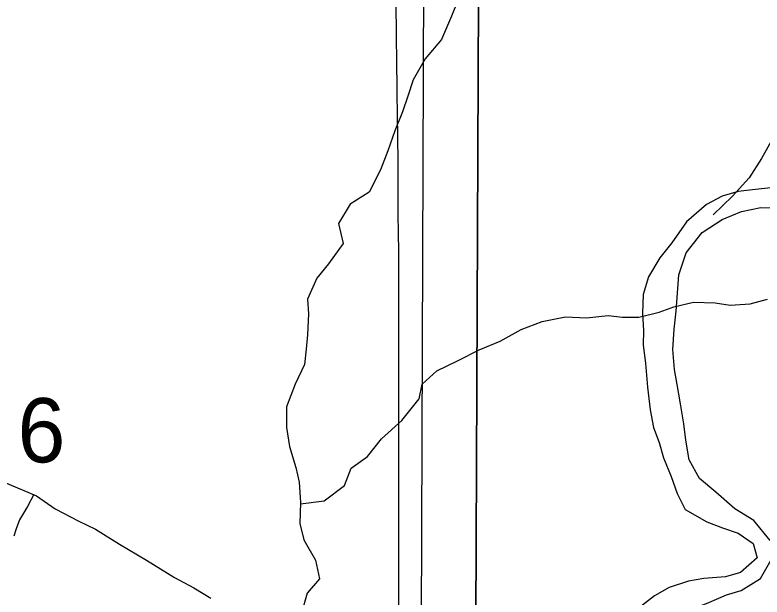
# Model space of a CAD drawing. Extents: x -21.1 to 50.3, y 0 to 22.1.
# Drawn here: x 3.1823 to 3.6686, y 18.2769 to 18.6561 of the extents above; entities that cross this region are included whole.
import ezdxf

# ---------------------------------------------------------------- set-up
doc = ezdxf.new("R2010")
doc.units = 0
for name, color, linetype in [('GM_X_Major_River', 7, 'Continuous'), ('GM_X_Minor_River', 7, 'Continuous'), ('GM_X_Section', 7, 'Continuous'), ('GM_X_Section_Text', 7, 'Continuous'), ('GM_X_State_Route', 7, 'Continuous')]:
    doc.layers.add(name, color=color, linetype=linetype)

msp = doc.modelspace()

# ---------------------------------------------------------------- linework, layer by layer
at = {"layer": 'GM_X_Major_River'}
msp.add_lwpolyline([(3.17432, 18.35222), (3.19639, 18.34289), (3.20858, 18.33425), (3.22381, 18.32639), (3.23484, 18.32116), (3.25046, 18.31141), (3.26798, 18.30091), (3.28627, 18.28965), (3.29883, 18.28291), (3.30988, 18.27616)], dxfattribs=at)
at = {"layer": 'GM_X_Minor_River'}
for points in [[(3.47062, 18.66546), (3.46645, 18.65522), (3.46, 18.64005), (3.44938, 18.62753), (3.44141, 18.61388), (3.43799, 18.60326), (3.43458, 18.59302), (3.42964, 18.5805), (3.42509, 18.5676), (3.42015, 18.55509), (3.41294, 18.54068), (3.40043, 18.53271), (3.39284, 18.52019)], [(3.80397, 18.65773), (3.79104, 18.65049), (3.7785, 18.64325), (3.76671, 18.636), (3.75455, 18.62648), (3.74277, 18.61848), (3.73021, 18.6158), (3.71728, 18.61313), (3.70587, 18.60779), (3.69409, 18.59979), (3.68345, 18.58912), (3.67548, 18.57542), (3.66827, 18.56248), (3.6603, 18.54992), (3.64928, 18.53812), (3.63674, 18.52593)], [(3.67429, 18.54348), (3.66441, 18.54244), (3.653, 18.54104), (3.64272, 18.5381), (3.63242, 18.53251), (3.61939, 18.52124), (3.60976, 18.50767), (3.60207, 18.49787), (3.59473, 18.48541), (3.5912, 18.47405), (3.59069, 18.46152), (3.59134, 18.4505), (3.59124, 18.441), (3.59263, 18.42921), (3.59399, 18.41362), (3.59574, 18.39879), (3.5979, 18.38737), (3.60159, 18.37746), (3.60453, 18.36755), (3.60934, 18.35535), (3.6134, 18.34429), (3.61861, 18.33398), (3.63257, 18.32586), (3.64278, 18.32196), (3.65299, 18.31844), (3.66279, 18.31188)], [(3.67382, 18.31367), (3.66333, 18.32669), (3.65088, 18.33442), (3.63846, 18.34518), (3.62792, 18.35402), (3.62122, 18.36624), (3.61907, 18.37918), (3.61766, 18.38983), (3.61552, 18.40277), (3.61337, 18.41533), (3.61157, 18.42522), (3.61057, 18.43815), (3.61146, 18.45143), (3.61272, 18.46319), (3.61449, 18.48673), (3.61919, 18.50111), (3.62957, 18.5143), (3.64257, 18.52291), (3.65515, 18.5281), (3.6677, 18.53063), (3.67909, 18.53052)], [(3.39284, 18.52019), (3.39587, 18.5073), (3.38639, 18.49402), (3.3788, 18.48454), (3.37273, 18.47088), (3.37348, 18.4614), (3.37272, 18.44775), (3.37195, 18.43826), (3.37081, 18.4284), (3.36474, 18.41551), (3.35904, 18.40072), (3.35904, 18.38744), (3.36093, 18.37493), (3.36509, 18.36127), (3.36736, 18.35179), (3.36811, 18.33852), (3.36772, 18.32487), (3.37037, 18.31425), (3.37795, 18.30097), (3.38059, 18.28883), (3.37263, 18.27935), (3.36883, 18.26646)], [(3.36809, 18.33767), (3.38365, 18.33966), (3.39692, 18.34952), (3.4011, 18.3609), (3.41172, 18.36849), (3.42082, 18.37987), (3.43409, 18.392), (3.44547, 18.40604), (3.44737, 18.41552), (3.45685, 18.42424), (3.47088, 18.43107), (3.48453, 18.4379), (3.49818, 18.44359), (3.51183, 18.45118), (3.52548, 18.45649), (3.54064, 18.45953), (3.55429, 18.45877), (3.56832, 18.46029), (3.57779, 18.45915), (3.5884, 18.45915), (3.60167, 18.46257), (3.61115, 18.46598), (3.62404, 18.46902), (3.63807, 18.46864), (3.64792, 18.46713), (3.66081, 18.46789), (3.67218, 18.47092)], [(3.19457, 18.34366), (3.19051, 18.33591), (3.18526, 18.32712), (3.18303, 18.3214), (3.18155, 18.31645)], [(3.66279, 18.31188), (3.66535, 18.30236), (3.65463, 18.29297), (3.64473, 18.29004), (3.63067, 18.28904), (3.62078, 18.28724), (3.60821, 18.28319), (3.59867, 18.27759), (3.58872, 18.27009), (3.57682, 18.25729), (3.5695, 18.24673), (3.56102, 18.23428), (3.54951, 18.22262), (3.53776, 18.22426), (3.53371, 18.23608), (3.53005, 18.24941), (3.51526, 18.25108), (3.50306, 18.24589), (3.49236, 18.23878), (3.48204, 18.23243), (3.46869, 18.22534), (3.45837, 18.21861)], [(3.58647, 18.23631), (3.59649, 18.25064), (3.6099, 18.26228), (3.62021, 18.26825), (3.6324, 18.27269), (3.64536, 18.27825), (3.65488, 18.2812), (3.66749, 18.28905), (3.67445, 18.30113)]]:
    msp.add_lwpolyline(points, dxfattribs=at)
at = {"layer": 'GM_X_Section'}
for points in [[(3.45029, 19.15441), (4.46024, 19.14326), (4.45293, 18.14262), (3.44648, 18.14125)], [(4.50596, 18.94006), (4.50247, 17.98887), (4.50289, 17.92975), (3.48086, 17.90781), (3.48506, 18.92038)], [(3.48506, 18.92038), (3.48086, 17.90781), (2.49066, 17.89119), (2.48311, 18.9064)]]:
    msp.add_lwpolyline(points, close=True, dxfattribs=at)
at = {"layer": 'GM_X_State_Route'}
msp.add_lwpolyline([(3.43227, 18.24572), (3.43215, 18.50202), (3.43184, 18.52634), (3.43173, 18.56095), (3.43132, 18.5913), (3.43111, 18.60512), (3.4308, 18.62882), (3.4307, 18.63869), (3.43059, 18.64877), (3.43028, 18.66789), (3.42997, 18.70323), (3.42986, 18.71165), (3.42872, 18.79895)], dxfattribs=at)

# ---------------------------------------------------------------- texts
at = {"layer": 'GM_X_Section_Text'}
msp.add_text('6', height=0.04186, rotation=0, dxfattribs=at).set_placement((3.18402, 18.36463))

doc.saveas('drawing.dxf')
